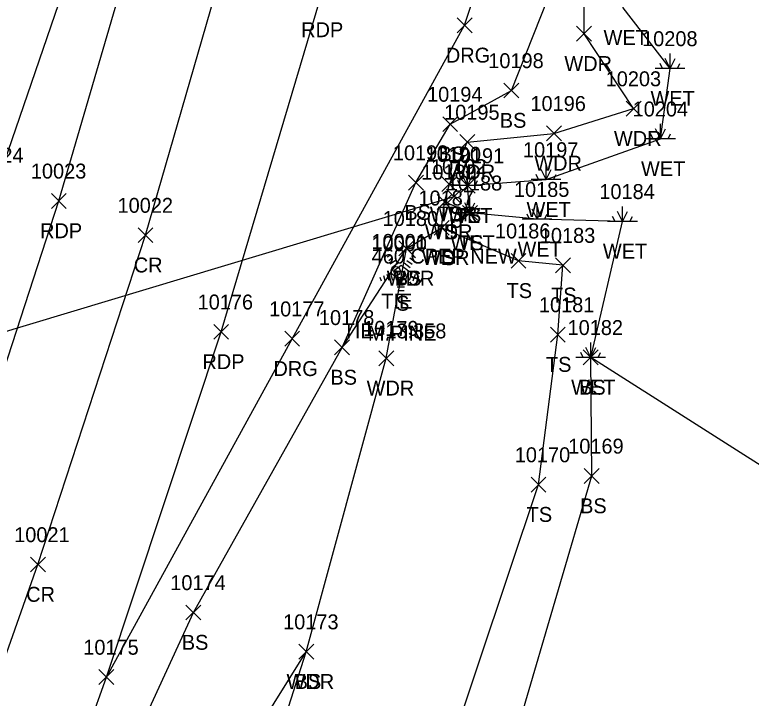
# Model space of a CAD drawing. Extents: x 1482574 to 1485769, y 580696 to 595649.
# Drawn here: x 1485074.8 to 1485173.6, y 580799.4 to 580891 of the extents above; entities that cross this region are included whole.
import ezdxf

# ---------------------------------------------------------------- set-up
doc = ezdxf.new("R2010")
doc.units = 0
for name, color, linetype in [('C_A', 7, 'Continuous'), ('C_C', 7, 'Continuous'), ('C_I', 7, 'Continuous'), ('CBP', 7, 'Continuous'), ('D_A', 7, 'Continuous'), ('D_C', 7, 'Continuous'), ('D_I', 7, 'Continuous'), ('D_TIC', 7, 'Continuous'), ('DCP', 7, 'Continuous'), ('L_A', 7, 'Continuous'), ('L_C', 7, 'Continuous'), ('L_I', 7, 'Continuous'), ('L_TIC', 7, 'Continuous'), ('LAWA', 7, 'Continuous'), ('LELB', 7, 'Continuous'), ('LTC', 7, 'Continuous'), ('LWET', 7, 'Continuous'), ('P_A', 7, 'Continuous'), ('P_I', 7, 'Continuous'), ('P_TIC', 7, 'Continuous'), ('PET', 7, 'Continuous'), ('PRC', 7, 'Continuous'), ('R_A', 7, 'Continuous'), ('R_I', 7, 'Continuous'), ('R_TIC', 7, 'Continuous'), ('RDG', 7, 'Continuous')]:
    doc.layers.add(name, color=color, linetype=linetype)

msp = doc.modelspace()

# ---------------------------------------------------------------- linework, layer by layer
at = {"layer": 'CBP'}
for radius in [0.625, 0.0833]:
    msp.add_circle((1485125.925, 580856.63), radius, dxfattribs=at)
at = {"layer": 'D_TIC'}
for points in [[(1485132.758, 580865.663), (1485134.758, 580867.663)], [(1485134.758, 580865.663), (1485132.758, 580867.663)]]:
    msp.add_lwpolyline(points, dxfattribs=at)
at = {"layer": 'DCP'}
msp.add_lwpolyline([(1485056.575, 580843.471), (1485133.758, 580866.663)], dxfattribs=at)
at = {"layer": 'L_TIC'}
for points in [[(1485150.198, 580887.479), (1485152.198, 580889.479)], [(1485152.198, 580887.479), (1485150.198, 580889.479)], [(1485140.449, 580879.87), (1485142.449, 580881.87)], [(1485142.449, 580879.87), (1485140.449, 580881.87)], [(1485156.846, 580877.443), (1485158.846, 580879.443)], [(1485158.846, 580877.443), (1485156.846, 580879.443)], [(1485132.238, 580875.364), (1485134.238, 580877.364)], [(1485134.238, 580875.364), (1485132.238, 580877.364)], [(1485146.165, 580874.126), (1485148.165, 580876.126)], [(1485148.165, 580874.126), (1485146.165, 580876.126)], [(1485134.53, 580872.952), (1485136.53, 580874.952)], [(1485136.53, 580872.952), (1485134.53, 580874.952)], [(1485127.648, 580867.517), (1485129.648, 580869.517)], [(1485129.648, 580867.517), (1485127.648, 580869.517)], [(1485132.13, 580867.317), (1485134.13, 580869.317)], [(1485134.13, 580867.317), (1485132.13, 580869.317)], [(1485132.13, 580867.317), (1485134.13, 580869.317)], [(1485134.13, 580867.317), (1485132.13, 580869.317)], [(1485134.576, 580867.121), (1485136.576, 580869.121)], [(1485136.576, 580867.121), (1485134.576, 580869.121)], [(1485131.474, 580864.927), (1485133.474, 580866.927)], [(1485133.474, 580864.927), (1485131.474, 580866.927)], [(1485131.474, 580864.927), (1485133.474, 580866.927)], [(1485133.474, 580864.927), (1485131.474, 580866.927)], [(1485134.881, 580863.463), (1485136.881, 580865.463)], [(1485136.881, 580863.463), (1485134.881, 580865.463)], [(1485131.085, 580861.453), (1485133.085, 580863.453)], [(1485133.085, 580861.453), (1485131.085, 580863.453)], [(1485131.085, 580861.453), (1485133.085, 580863.453)], [(1485133.085, 580861.453), (1485131.085, 580863.453)], [(1485126.362, 580858.705), (1485128.362, 580860.705)], [(1485128.362, 580858.705), (1485126.362, 580860.705)], [(1485126.362, 580858.705), (1485128.362, 580860.705)], [(1485128.362, 580858.705), (1485126.362, 580860.705)], [(1485141.399, 580857.036), (1485143.399, 580859.036)], [(1485143.399, 580857.036), (1485141.399, 580859.036)], [(1485147.368, 580856.44), (1485149.368, 580858.44)], [(1485149.368, 580856.44), (1485147.368, 580858.44)], [(1485146.679, 580847.144), (1485148.679, 580849.144)], [(1485148.679, 580847.144), (1485146.679, 580849.144)], [(1485117.726, 580845.421), (1485119.726, 580847.421)], [(1485119.726, 580845.421), (1485117.726, 580847.421)], [(1485117.726, 580845.421), (1485119.726, 580847.421)], [(1485119.726, 580845.421), (1485117.726, 580847.421)], [(1485151.09, 580844.082), (1485153.09, 580846.082)], [(1485153.09, 580844.082), (1485151.09, 580846.082)], [(1485123.667, 580843.971), (1485125.667, 580845.971)], [(1485125.667, 580843.971), (1485123.667, 580845.971)], [(1485151.23, 580828.179), (1485153.23, 580830.179)], [(1485153.23, 580828.179), (1485151.23, 580830.179)], [(1485144.091, 580827.021), (1485146.091, 580829.021)], [(1485146.091, 580827.021), (1485144.091, 580829.021)], [(1485097.784, 580809.871), (1485099.784, 580811.871)], [(1485099.784, 580809.871), (1485097.784, 580811.871)], [(1485112.925, 580804.616), (1485114.925, 580806.616)], [(1485114.925, 580804.616), (1485112.925, 580806.616)], [(1485112.925, 580804.616), (1485114.925, 580806.616)], [(1485114.925, 580804.616), (1485112.925, 580806.616)]]:
    msp.add_lwpolyline(points, dxfattribs=at)
at = {"layer": 'LAWA'}
msp.add_lwpolyline([(1485090.092, 580767.38), (1485113.925, 580805.616), (1485124.667, 580844.971), (1485127.362, 580859.705), (1485132.085, 580862.453), (1485132.474, 580865.927), (1485133.13, 580868.317), (1485135.53, 580873.952), (1485147.165, 580875.126), (1485157.846, 580878.443), (1485151.198, 580888.479), (1485151.287, 580905.746), (1485152.481, 580913.284), (1485162.051, 580941.521), (1485162.559, 580967.491), (1485161.388, 581018.868), (1485163.444, 581059.471), (1485163.193, 581091.441), (1485177.832, 581136.406)], dxfattribs=at)
at = {"layer": 'LELB'}
for points in [[(1485046.938, 580776.996), (1485062.945, 580821.645), (1485067.851, 580840.242), (1485070.562, 580856.807), (1485072.311, 580868.197), (1485086.478, 580909.371), (1485099.599, 580947.351), (1485113.38, 581011.442), (1485123.36, 581058.794), (1485130.188, 581108.035), (1485133.211, 581140.808)], [(1485118.726, 580846.421), (1485128.648, 580868.517), (1485133.238, 580876.364), (1485141.449, 580880.87), (1485151.287, 580905.746)], [(1485133.13, 580868.317), (1485135.576, 580868.121)], [(1485135.881, 580864.463), (1485132.474, 580865.927)], [(1485123.703, 580758.581), (1485129.006, 580779.946), (1485145.091, 580828.021), (1485147.679, 580848.144), (1485148.368, 580857.44), (1485142.399, 580858.036), (1485132.085, 580862.453)], [(1485079.362, 580768.575), (1485098.784, 580810.871), (1485118.726, 580846.421), (1485127.362, 580859.705)], [(1485123.703, 580758.581), (1485138.168, 580781.173), (1485152.23, 580829.179), (1485152.09, 580845.082)], [(1485101.232, 580765.793), (1485113.925, 580805.616)]]:
    msp.add_lwpolyline(points, dxfattribs=at)
at = {"layer": 'LTC'}
for p, q in [((1485124.782, 580858.547), (1485125.136, 580858.804)), ((1485124.991, 580858.082), (1485125.52, 580858.466)), ((1485125.201, 580857.616), (1485125.905, 580858.127)), ((1485127.438, 580858.091), (1485128.117, 580857.597)), ((1485127.809, 580858.439), (1485128.358, 580858.04)), ((1485128.18, 580858.787), (1485128.599, 580858.483)), ((1485125.41, 580857.15), (1485126.289, 580857.788)), ((1485125.635, 580856.695), (1485126.647, 580857.429)), ((1485126.647, 580857.429), (1485127.644, 580856.704)), ((1485127.067, 580857.742), (1485127.876, 580857.154)), ((1485124.27, 580856.043), (1485124.481, 580855.391)), ((1485124.725, 580856.259), (1485124.996, 580855.424)), ((1485125.18, 580856.476), (1485125.511, 580855.457)), ((1485125.635, 580856.695), (1485126.022, 580855.502)), ((1485127.644, 580856.704), (1485127.252, 580855.502)), ((1485128.081, 580856.434), (1485127.743, 580855.394)), ((1485128.526, 580856.183), (1485128.238, 580855.299)), ((1485128.97, 580855.933), (1485128.733, 580855.204)), ((1485123.814, 580855.826), (1485123.966, 580855.358)), ((1485127.252, 580855.502), (1485126.022, 580855.502)), ((1485127.214, 580855.002), (1485126.07, 580855.002)), ((1485129.415, 580855.683), (1485129.228, 580855.109)), ((1485127.13, 580854.502), (1485126.142, 580854.502)), ((1485127.047, 580854.002), (1485126.215, 580854.002)), ((1485126.963, 580853.502), (1485126.288, 580853.502))]:
    msp.add_line(p, q, dxfattribs=at)
at = {"layer": 'LWET'}
for p, q in [((1485162.736, 580883.821), (1485162.736, 580885.821)), ((1485162.736, 580883.821), (1485162.069, 580885.154)), ((1485162.736, 580883.821), (1485163.402, 580885.154)), ((1485164.736, 580883.821), (1485160.736, 580883.821)), ((1485161.736, 580883.821), (1485161.402, 580884.487)), ((1485163.736, 580883.821), (1485164.069, 580884.487)), ((1485161.465, 580874.392), (1485160.799, 580875.726)), ((1485161.465, 580874.392), (1485161.465, 580876.392)), ((1485161.465, 580874.392), (1485162.132, 580875.726)), ((1485160.465, 580874.392), (1485160.132, 580875.059)), ((1485162.465, 580874.392), (1485162.799, 580875.059)), ((1485163.465, 580874.392), (1485159.465, 580874.392)), ((1485146.104, 580868.931), (1485146.104, 580870.931)), ((1485135.576, 580868.121), (1485135.576, 580870.121)), ((1485146.104, 580868.931), (1485145.438, 580870.264)), ((1485146.104, 580868.931), (1485146.771, 580870.264)), ((1485134.576, 580868.121), (1485134.243, 580868.788)), ((1485135.576, 580868.121), (1485134.91, 580869.455)), ((1485135.576, 580868.121), (1485136.243, 580869.455)), ((1485136.576, 580868.121), (1485136.91, 580868.788)), ((1485148.104, 580868.931), (1485144.104, 580868.931)), ((1485145.104, 580868.931), (1485144.771, 580869.597)), ((1485147.104, 580868.931), (1485147.438, 580869.597)), ((1485137.576, 580868.121), (1485133.576, 580868.121)), ((1485135.881, 580864.463), (1485135.215, 580865.796)), ((1485135.881, 580864.463), (1485135.881, 580866.463)), ((1485135.881, 580864.463), (1485136.548, 580865.796)), ((1485134.881, 580864.463), (1485134.548, 580865.13)), ((1485136.881, 580864.463), (1485137.215, 580865.13)), ((1485144.895, 580863.607), (1485144.228, 580864.94)), ((1485144.895, 580863.607), (1485144.895, 580865.607)), ((1485144.895, 580863.607), (1485145.561, 580864.94)), ((1485156.352, 580863.319), (1485156.352, 580865.319)), ((1485137.881, 580864.463), (1485133.881, 580864.463)), ((1485143.895, 580863.607), (1485143.561, 580864.273)), ((1485145.895, 580863.607), (1485146.228, 580864.273)), ((1485155.352, 580863.319), (1485155.019, 580863.986)), ((1485156.352, 580863.319), (1485155.686, 580864.653)), ((1485156.352, 580863.319), (1485157.019, 580864.653)), ((1485157.352, 580863.319), (1485157.686, 580863.986)), ((1485146.895, 580863.607), (1485142.895, 580863.607)), ((1485158.352, 580863.319), (1485154.352, 580863.319)), ((1485152.09, 580845.082), (1485152.09, 580847.082)), ((1485152.09, 580845.082), (1485151.424, 580846.416)), ((1485152.09, 580845.082), (1485152.757, 580846.416)), ((1485154.09, 580845.082), (1485150.09, 580845.082)), ((1485151.09, 580845.082), (1485150.757, 580845.749)), ((1485153.09, 580845.082), (1485153.424, 580845.749))]:
    msp.add_line(p, q, dxfattribs=at)
msp.add_lwpolyline([(1485187.209, 580726.15), (1485182.006, 580778.93), (1485180.372, 580827.108), (1485152.09, 580845.082), (1485156.352, 580863.319), (1485144.895, 580863.607), (1485135.881, 580864.463), (1485135.576, 580868.121), (1485146.104, 580868.931), (1485161.465, 580874.392), (1485162.736, 580883.821), (1485156.442, 580891.971), (1485159.974, 580906.474), (1485167.399, 580920.375), (1485188.456, 580918.417), (1485209.306, 580890.099), (1485243.947, 580890.837), (1485237.051, 580923.485), (1485236.366, 580950.705), (1485240.416, 580999.189)], dxfattribs=at)
at = {"layer": 'P_TIC'}
for points in [[(1485079.724, 580865.066), (1485081.724, 580867.066)], [(1485081.724, 580865.066), (1485079.724, 580867.066)], [(1485091.354, 580860.472), (1485093.354, 580862.472)], [(1485093.354, 580860.472), (1485091.354, 580862.472)], [(1485101.508, 580847.507), (1485103.508, 580849.507)], [(1485103.508, 580847.507), (1485101.508, 580849.507)], [(1485076.919, 580816.306), (1485078.919, 580818.306)], [(1485078.919, 580816.306), (1485076.919, 580818.306)], [(1485086.11, 580801.211), (1485088.11, 580803.211)], [(1485088.11, 580801.211), (1485086.11, 580803.211)]]:
    msp.add_lwpolyline(points, dxfattribs=at)
at = {"layer": 'PET'}
for points in [[(1485050.429, 580776.091), (1485065.965, 580820.78), (1485080.724, 580866.066), (1485093.149, 580908.622), (1485102.737, 580946.524), (1485117.016, 581010.836), (1485125.369, 581058.408), (1485132.207, 581107.901), (1485135.951, 581140.585)], [(1485075.284, 580769.139), (1485087.11, 580802.211), (1485102.508, 580848.507), (1485115.757, 580893.023), (1485126.66, 580933.617), (1485135.553, 580972.24), (1485145.039, 581020.228), (1485151.596, 581060.97), (1485155.933, 581092.603), (1485160.974, 581136.636)]]:
    msp.add_lwpolyline(points, dxfattribs=at)
at = {"layer": 'PRC'}
msp.add_lwpolyline([(1485061.993, 580772.26), (1485077.919, 580817.306), (1485092.354, 580861.472), (1485105.403, 580906.667), (1485114.947, 580943.575), (1485128.714, 581008.466), (1485136.886, 581056.712), (1485144.398, 581107.111), (1485147.832, 581139.156)], dxfattribs=at)
at = {"layer": 'R_TIC'}
for points in [[(1485134.171, 580888.616), (1485136.171, 580890.616)], [(1485136.171, 580888.616), (1485134.171, 580890.616)], [(1485111.038, 580846.58), (1485113.038, 580848.58)], [(1485113.038, 580846.58), (1485111.038, 580848.58)], [(1485086.11, 580801.211), (1485088.11, 580803.211)], [(1485088.11, 580801.211), (1485086.11, 580803.211)]]:
    msp.add_lwpolyline(points, dxfattribs=at)
at = {"layer": 'RDG'}
msp.add_lwpolyline([(1485087.11, 580802.211), (1485112.038, 580847.58), (1485135.171, 580889.616), (1485143.671, 580915.018), (1485144.599, 580944.812), (1485135.553, 580972.24)], dxfattribs=at)

# ---------------------------------------------------------------- texts
at = {"layer": 'C_A'}
msp.add_text('TIE', height=2, dxfattribs=at).set_placement((1485124.004, 580851.63))
at = {"layer": 'C_C'}
msp.add_text('TIE=13.358', height=2, dxfattribs=at).set_placement((1485118.823, 580847.63))
at = {"layer": 'C_I'}
msp.add_text('10001', height=2, dxfattribs=at).set_placement((1485122.666, 580859.63))
at = {"layer": 'D_A'}
msp.add_text('P', height=2, dxfattribs=at).set_placement((1485133.136, 580861.663))
at = {"layer": 'D_C'}
msp.add_text('460 CPEP NEW', height=2, dxfattribs=at).set_placement((1485122.703, 580857.663))
at = {"layer": 'D_I'}
msp.add_text('10192', height=2, dxfattribs=at).set_placement((1485130.656, 580869.663))
at = {"layer": 'L_A'}
for s, p in [('WET', (1485153.82, 580886.971)), ('WDR', (1485148.56, 580883.479)), ('WET', (1485160.114, 580878.821)), ('BS', (1485139.89, 580875.87)), ('WDR', (1485155.208, 580873.443)), ('BS', (1485131.679, 580871.364)), ('WDR', (1485144.527, 580870.126)), ('WDR', (1485132.892, 580868.952)), ('WET', (1485158.843, 580869.392)), ('WET', (1485143.482, 580863.931)), ('BS', (1485127.089, 580863.517)), ('WDR', (1485130.492, 580863.317)), ('TS', (1485131.539, 580863.317)), ('WET', (1485132.954, 580863.121)), ('TS', (1485133.986, 580863.121)), ('WDR', (1485129.836, 580860.927)), ('TS', (1485130.883, 580860.927)), ('WET', (1485133.259, 580859.463)), ('TS', (1485134.291, 580859.463)), ('WET', (1485142.273, 580858.607)), ('WET', (1485153.73, 580858.319)), ('WDR', (1485129.447, 580857.453)), ('TS', (1485130.494, 580857.453)), ('WDR', (1485124.725, 580854.705)), ('BS', (1485125.803, 580854.705)), ('TS', (1485140.809, 580853.036)), ('TS', (1485146.777, 580852.44)), ('S', (1485125.972, 580851.339)), ('TS', (1485146.089, 580843.144)), ('BS', (1485117.167, 580841.421)), ('BS', (1485117.167, 580841.421)), ('WET', (1485149.468, 580840.082)), ('BS', (1485150.531, 580840.082)), ('WDR', (1485122.029, 580839.971)), ('BS', (1485150.671, 580824.179)), ('TS', (1485143.501, 580823.021)), ('BS', (1485097.225, 580805.871)), ('WDR', (1485111.288, 580800.616)), ('BS', (1485112.366, 580800.616))]:
    msp.add_text(s, height=2, dxfattribs=at).set_placement(p)
at = {"layer": 'L_C'}
msp.add_text('M.PINE', height=2, dxfattribs=at).set_placement((1485122.193, 580847.339))
at = {"layer": 'L_I'}
for s, p in [('10208', (1485158.988, 580886.821)), ('10198', (1485138.347, 580883.87)), ('10203', (1485154.098, 580881.443)), ('10194', (1485130.136, 580879.364)), ('10196', (1485144.007, 580878.126)), ('10195', (1485132.428, 580876.952)), ('10204', (1485157.717, 580877.392)), ('10197', (1485143.002, 580871.931)), ('10024', (1485068.563, 580871.197)), ('10193', (1485125.546, 580871.517)), ('10190', (1485129.941, 580871.317)), ('10190', (1485129.941, 580871.317)), ('10191', (1485133.041, 580871.121)), ('10191', (1485133.041, 580871.121)), ('10189', (1485129.363, 580868.927)), ('10189', (1485129.363, 580868.927)), ('10188', (1485132.779, 580867.463)), ('10188', (1485132.779, 580867.463)), ('10185', (1485141.792, 580866.607)), ('10184', (1485153.25, 580866.319)), ('10187', (1485128.982, 580865.453)), ('10187', (1485128.982, 580865.453)), ('10180', (1485124.173, 580862.705)), ('10180', (1485124.173, 580862.705)), ('10186', (1485139.242, 580861.036)), ('10183', (1485145.265, 580860.44)), ('10000', (1485122.673, 580859.339)), ('10181', (1485145.144, 580851.144)), ('10178', (1485115.624, 580849.421)), ('10178', (1485115.624, 580849.421)), ('10179', (1485121.557, 580847.971)), ('10182', (1485148.988, 580848.082)), ('10182', (1485148.988, 580848.082)), ('10169', (1485149.073, 580832.179)), ('10170', (1485141.902, 580831.021)), ('10174', (1485095.681, 580813.871)), ('10173', (1485110.823, 580808.616)), ('10173', (1485110.823, 580808.616))]:
    msp.add_text(s, height=2, dxfattribs=at).set_placement(p)
at = {"layer": 'LTC'}
msp.add_text('.', height=1.037, rotation=270, dxfattribs=at).set_placement((1485126.529, 580856.443))
at = {"layer": 'P_A'}
for s, p in [('RDP', (1485113.245, 580888.023)), ('RDP', (1485078.212, 580861.066)), ('CR', (1485090.787, 580856.472)), ('RDP', (1485099.996, 580843.507)), ('CR', (1485076.352, 580812.306))]:
    msp.add_text(s, height=2, dxfattribs=at).set_placement(p)
at = {"layer": 'P_I'}
for s, p in [('10023', (1485076.976, 580869.066)), ('10022', (1485088.606, 580864.472)), ('10176', (1485099.35, 580851.507)), ('10021', (1485074.738, 580820.306)), ('10175', (1485084.008, 580805.211))]:
    msp.add_text(s, height=2, dxfattribs=at).set_placement(p)
at = {"layer": 'R_A'}
for p in [(1485132.659, 580884.616), (1485109.526, 580842.58)]:
    msp.add_text('DRG', height=2, dxfattribs=at).set_placement(p)
at = {"layer": 'R_I'}
for s, p in [('10177', (1485108.936, 580850.58)), ('10175', (1485084.008, 580805.211))]:
    msp.add_text(s, height=2, dxfattribs=at).set_placement(p)

doc.saveas('drawing.dxf')
